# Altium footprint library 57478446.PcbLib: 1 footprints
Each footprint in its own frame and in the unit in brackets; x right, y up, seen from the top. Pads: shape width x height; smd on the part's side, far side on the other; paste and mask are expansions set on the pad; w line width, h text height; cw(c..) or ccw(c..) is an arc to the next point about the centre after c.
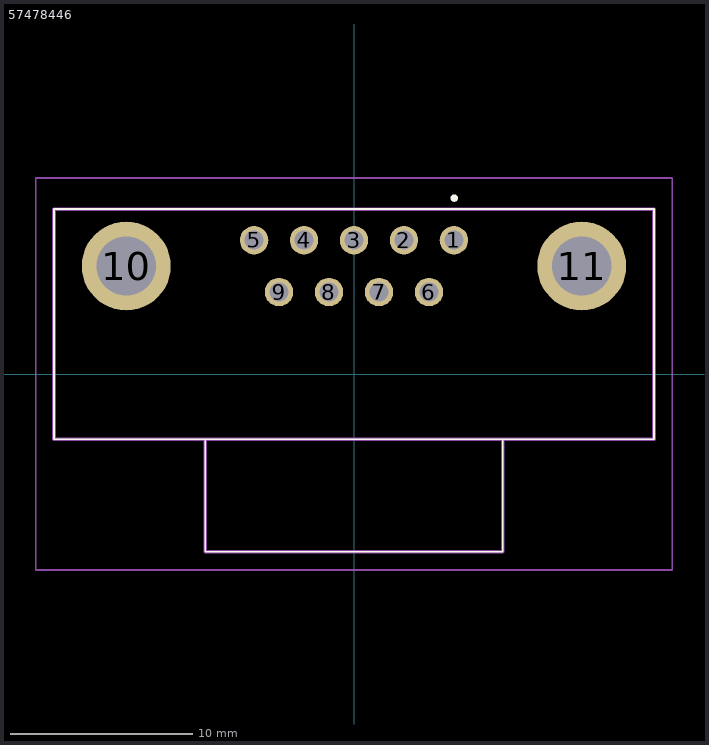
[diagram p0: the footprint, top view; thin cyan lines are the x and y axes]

## 57478446 [mil]
pads (11):
  round 61.5 hole 41: 1(215.98,289.13) 2(107.99,289.13) 3(0,289.13) 4(-107.99,289.13) 5(-215.98,289.13) 6(162.01,177.13) 7(54.02,177.13) 8(-54.02,177.13) 9(-162.01,177.13)
  round 192 hole 128: 10(-492.01,233.11) 11(492.01,233.11)
Top Overlay:
  lines w3.94: -321.5,-140.87 -321.5,-383.86 321.5,-383.86 321.5,-140.87 ; -647.99,-140.87 647.99,-140.87 647.99,356.14 -647.99,356.14 -647.99,-140.87
  lines w7.87: 212.6,379.92 212.6,379.92 ; 212.6,379.92 cw(c216.54,379.92) 220.47,379.92 ; 212.6,379.92 ccw(c216.54,379.92) 220.47,379.92 ; 220.47,379.92 220.47,379.92
Mechanical 15:
  lines w7.87: -321.5,-140.87 -321.5,-383.86 321.5,-383.86 321.5,-140.87 ; -647.99,-140.87 647.99,-140.87 647.99,356.14 -647.99,356.14 -647.99,-140.87
Mechanical 20:
  lines w3.94: -687.36,-423.23 687.36,-423.23 687.36,423.23 -687.36,423.23 -687.36,-423.23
